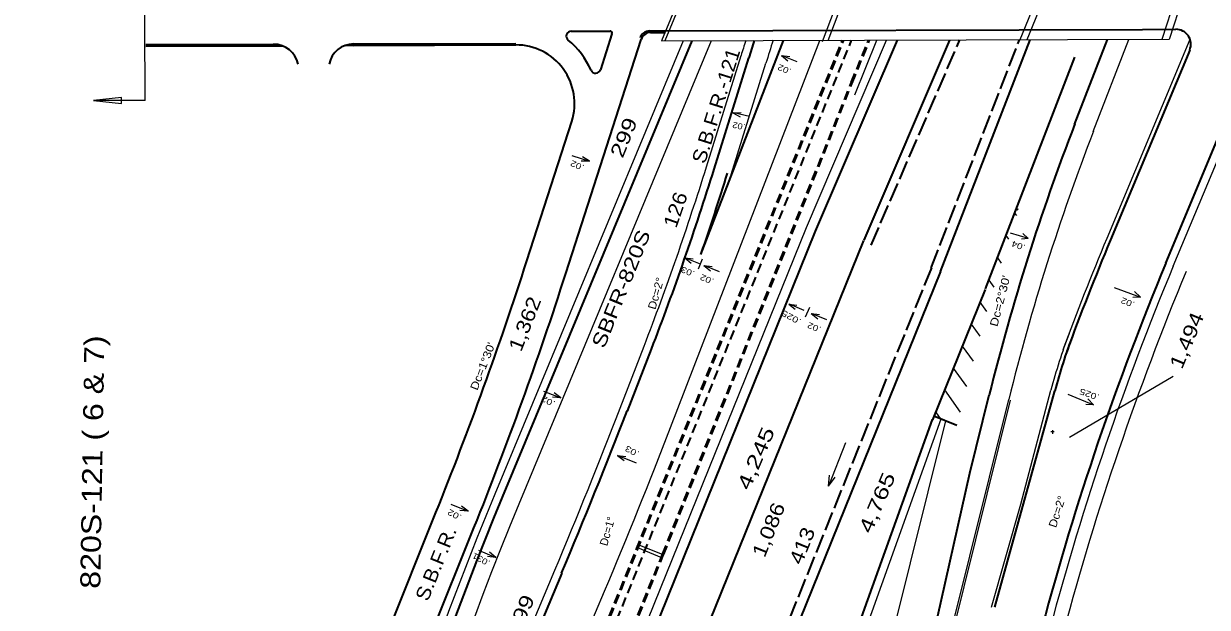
# Model space of a CAD drawing. Extents: x 2354993 to 2372084, y 6966390 to 6990057.
# Drawn here: x 2364091 to 2365274, y 6979897 to 6980481 of the extents above; entities that cross this region are included whole.
import ezdxf

# ---------------------------------------------------------------- set-up
doc = ezdxf.new("R2010")
doc.units = 0
doc.header["$LTSCALE"] = 3.2
doc.linetypes.add('LONG_DASHED', pattern=[7.5, 6, -1.5])
doc.linetypes.add('MEDIUM_DASHED', pattern=[4.5, 3, -1.5])
for name, color, linetype, lineweight in [('1', 7, 'Continuous', 13), ('12', 7, 'Continuous', 13), ('13', 7, 'Continuous', 13), ('14', 7, 'Continuous', 13), ('15', 7, 'Continuous', 13), ('17', 7, 'Continuous', 13), ('19', 7, 'Continuous', 13), ('2', 7, 'Continuous', 35), ('23', 7, 'Continuous', 13), ('4', 7, 'Continuous', 13), ('5', 7, 'Continuous', 35), ('63', 7, 'Continuous', 35), ('7', 7, 'Continuous', 13), ('9', 7, 'Continuous', 13)]:
    doc.layers.add(name, color=color, linetype=linetype, lineweight=lineweight)

msp = doc.modelspace()

# ---------------------------------------------------------------- linework, layer by layer
at = {"layer": '1', "lineweight": 35}
for p, q in [((2365083.088, 6980295.695), (2365084.953, 6980294.974)), ((2365051.927, 6980215.049), (2364999.207, 6980084.818))]:
    msp.add_line(p, q, dxfattribs=at)
at = {"layer": '1'}
for p, q in [((2365121.023, 6980072.57), (2365117.523, 6980072.57)), ((2365119.273, 6980074.32), (2365119.273, 6980070.82))]:
    msp.add_line(p, q, dxfattribs=at)
at = {"layer": '12'}
for p, q in [((2364889.34, 6980463.063), (2364934.323, 6980581.712)), ((2364895.069, 6980464.071), (2364938.998, 6980579.939)), ((2365133.691, 6980580.838), (2365086.673, 6980464.691)), ((2365140.767, 6980580.861), (2365093.748, 6980464.714)), ((2365273.39, 6980581.292), (2365235.902, 6980464.902)), ((2365263.831, 6980574.448), (2365228.608, 6980465.09)), ((2364704.438, 6979956.949), (2364728.538, 6979947.192))]:
    msp.add_line(p, q, dxfattribs=at)
at = {"layer": '13', "lineweight": 35}
for p, q in [((2365036.612, 6980031.444), (2365056.061, 6980109.786)), ((2364922.585, 6979522.917), (2365036.612, 6980031.444))]:
    msp.add_line(p, q, dxfattribs=at)
at = {"layer": '14'}
msp.add_line((2364895.323, 6980018.418), (2364901.939, 6980027.303), dxfattribs=at)
msp.add_lwpolyline([(2364912.252, 6980061.865), (2364895.323, 6980018.418), (2364896.266, 6980029.456)], dxfattribs=at)
at = {"layer": '15'}
msp.add_line((2364212.059, 6980404.032), (2364160.649, 6980403.865), dxfattribs=at)
msp.add_lwpolyline([(2364212.059, 6980404.032), (2364211.303, 6980637.104), (2364159.893, 6980636.937), (2364187.903, 6980634.029), (2364187.883, 6980640.028), (2364159.893, 6980636.937)], dxfattribs=at)
msp.add_lwpolyline([(2364160.649, 6980403.865), (2364188.659, 6980400.956), (2364188.639, 6980406.955)], close=True, dxfattribs=at)
at = {"layer": '17'}
for p, q in [((2365095.189, 6980265.952), (2365077.196, 6980271.228)), ((2365095.104, 6980266.029), (2365089.771, 6980271.008)), ((2365094.987, 6980266.028), (2365088.195, 6980265.248))]:
    msp.add_line(p, q, dxfattribs=at)
at = {"layer": '19'}
for p, q in [((2364848.319, 6980448.928), (2364854.815, 6980443.747)), ((2364848.319, 6980448.928), (2364856.571, 6980447.946)), ((2364863.906, 6980442.526), (2364849.11, 6980448.709)), ((2364799.753, 6980391.639), (2364808.048, 6980392.134)), ((2364799.753, 6980391.639), (2364807.064, 6980387.691)), ((2364816.228, 6980388.1), (2364800.57, 6980391.564)), ((2364638.595, 6980348.957), (2364656.429, 6980343.169)), ((2364656.429, 6980343.169), (2364648.126, 6980343.473)), ((2364656.429, 6980343.169), (2364649.532, 6980347.801)), ((2364751.674, 6980246.584), (2364758.17, 6980241.403)), ((2364751.674, 6980246.584), (2364759.926, 6980245.602)), ((2364767.261, 6980240.182), (2364752.465, 6980246.365)), ((2364769.185, 6980245.227), (2364764.875, 6980235.276)), ((2364770.828, 6980238.995), (2364777.324, 6980233.814)), ((2364770.828, 6980238.995), (2364779.08, 6980238.013)), ((2364786.415, 6980232.593), (2364771.619, 6980238.776)), ((2364855.541, 6980200.419), (2364862.037, 6980195.238)), ((2364855.541, 6980200.419), (2364863.793, 6980199.437)), ((2364871.128, 6980194.017), (2364856.332, 6980200.2)), ((2364876.405, 6980197.169), (2364872.095, 6980187.218)), ((2365207.175, 6980207.287), (2365199.555, 6980207.167)), ((2364878.048, 6980190.937), (2364884.544, 6980185.756)), ((2364878.048, 6980190.937), (2364886.3, 6980189.955)), ((2364893.635, 6980184.535), (2364878.839, 6980190.718)), ((2364610.341, 6980113.456), (2364627.785, 6980106.582)), ((2364627.785, 6980106.582), (2364619.516, 6980107.397)), ((2364627.785, 6980106.582), (2364621.186, 6980111.63)), ((2365160.351, 6980099.839), (2365152.732, 6980099.987)), ((2364684.446, 6980049.11), (2364692.709, 6980048.216)), ((2364517.739, 6980000.366), (2364535.115, 6979993.323)), ((2364535.115, 6979993.323), (2364528.565, 6979998.435)), ((2364535.115, 6979993.323), (2364526.855, 6979994.218)), ((2364545.495, 6979954.387), (2364562.777, 6979947.116)), ((2364562.777, 6979947.116), (2364556.295, 6979952.313)), ((2364562.777, 6979947.116), (2364554.529, 6979948.119))]:
    msp.add_line(p, q, dxfattribs=at)
for points in [[(2365181.045, 6980216.968), (2365207.175, 6980207.287), (2365201.372, 6980212.914)], [(2365134.575, 6980110.427), (2365160.351, 6980099.839), (2365154.747, 6980105.667)], [(2364703.322, 6980041.457), (2364684.446, 6980049.11), (2364690.995, 6980044)]]:
    msp.add_lwpolyline(points, dxfattribs=at)
at = {"layer": '2'}
for p, q in [((2364638.192, 6980473.229), (2364676.956, 6980473.353)), ((2364678.866, 6980470.741), (2364667.27, 6980434.672)), ((2364716.429, 6980473.483), (2365209.079, 6980475.077)), ((2364717.51, 6980471.986), (2364731.864, 6980472.033)), ((2364758.63, 6980463.629), (2364569.087, 6980007.233)), ((2364632.777, 6980231.022), (2364708.023, 6980465.047)), ((2364767.688, 6980249.927), (2364850.216, 6980463.926)), ((2364882.46, 6980273.331), (2364964.36, 6980464.295)), ((2364930.859, 6980264.426), (2365016.654, 6980464.464)), ((2365007.434, 6980233.06), (2365096.929, 6980464.724)), ((2364780.996, 6980335.421), (2364815.568, 6980446.589)), ((2365052.209, 6980215.763), (2365141.704, 6980447.427)), ((2364593.745, 6980243.573), (2364638.621, 6980383.141)), ((2364658.462, 6979719.253), (2364882.46, 6980273.331)), ((2364697.647, 6979688.336), (2364930.731, 6980264.109)), ((2365007.434, 6980233.06), (2364819.815, 6979769.595)), ((2364694.499, 6980093.497), (2364718.352, 6980155.347)), ((2364345.135, 6979599.119), (2364502.883, 6979991.918)), ((2364459.929, 6979774.94), (2364540.926, 6979976.626)), ((2364518.842, 6979669.717), (2364629.05, 6979931.257))]:
    msp.add_line(p, q, dxfattribs=at)
at = {"layer": '2', "linetype": 'LONG_DASHED'}
for p, q in [((2364937.909, 6980259.273), (2365026.649, 6980464.497)), ((2364998.106, 6980236.664), (2365086.195, 6980464.689)), ((2364998.165, 6980236.812), (2364810.546, 6979773.347))]:
    msp.add_line(p, q, dxfattribs=at)
at = {"layer": '2', "lineweight": 13}
msp.add_line((2365256.568, 6980465.111), (2365173.563, 6980266.128), dxfattribs=at)
at = {"layer": '2'}
for centre, radius, start, end in [((2364638.208, 6980468.229), 5, 90.18352, 230.55088), ((2364676.962, 6980471.353), 2, 342.17766, 90.18286), ((2364716.461, 6980463.483), 10, 90.18543, 162.29546), ((2364717.543, 6980461.986), 10, 90.18655, 162.17584), ((2364582.929, 6980401.048), 58.5, 342.17569, 90.18757), ((2364582.928, 6980401.048), 82, 23.83292, 50.55088), ((2370300.051, 6978740.971), 5743.578, 162.54462, 162.72484), ((2364662.51, 6980436.202), 5, 203.83292, 342.17739), ((2362045.437, 6981186.146), 2864.789, 338.91107, 342.72496), ((2362045.437, 6981186.146), 2878.788, 341.04639, 342.72496), ((2360994.978, 6981400.695), 3780.219, 338.11957, 342.17569), ((2360994.975, 6981400.684), 3821.219, 338.11954, 342.17584), ((2359382.264, 6982142.156), 5693.004, 337.15034, 338.91091), ((2367605.673, 6978746.13), 3288.045, 157.44674, 182.51497)]:
    msp.add_arc(centre, radius, start, end, dxfattribs=at)
at = {"layer": '2', "lineweight": 13}
for centre, radius, start, end in [((2367865.717, 6979143.099), 2917, 157.35659, 159.70903), ((2365704.789, 6979956.656), 608, 159.3693, 164.95986)]:
    msp.add_arc(centre, radius, start, end, dxfattribs=at)
at = {"layer": '23'}
msp.add_arc((2367865.518, 6979143.17), 2830.789, 157.35649, 165.06774, dxfattribs=at)
at = {"layer": '4'}
for p, q in [((2364749.956, 6980463.601), (2364561.699, 6980010.301)), ((2364778.146, 6980463.692), (2364585.71, 6980000.329)), ((2364737.418, 6980076.945), (2364886.702, 6980464.044)), ((2364773.357, 6980337.797), (2364807.929, 6980448.965)), ((2364798.185, 6980330.076), (2364832.756, 6980441.239)), ((2364687.035, 6980096.375), (2364710.887, 6980158.227)), ((2364511.47, 6979672.823), (2364621.678, 6979934.363)), ((2364586.141, 6979710.964), (2364671.441, 6979913.394))]:
    msp.add_line(p, q, dxfattribs=at)
for centre, radius, start, end in [((2370300.051, 6978740.971), 5751.578, 162.56997, 162.72484), ((2370300.048, 6978740.957), 5725.578, 162.48367, 162.72475), ((2362045.437, 6981186.146), 2856.789, 338.91107, 342.72496), ((2359382.264, 6982142.156), 5685.578, 337.15034, 338.91091), ((2359382.265, 6982142.155), 5739.578, 337.15034, 338.91091), ((2367605.673, 6978746.13), 3296.044, 157.44674, 174.9586), ((2367605.673, 6978746.13), 3270.045, 157.44674, 184.53246)]:
    msp.add_arc(centre, radius, start, end, dxfattribs=at)
at = {"layer": '5', "lineweight": 13}
for p, q in [((2364776.569, 6980579.679), (2364728.333, 6980463.531)), ((2364779.822, 6980579.689), (2364731.586, 6980463.541)), ((2364728.333, 6980463.531), (2365235.989, 6980465.174)), ((2364873.225, 6980277.168), (2364953.464, 6980464.26)), ((2364921.552, 6980409.674), (2364943.79, 6980464.228)), ((2365160.069, 6980372.867), (2365195.679, 6980465.044)), ((2365240.01, 6980238.403), (2365312.776, 6980412.838)), ((2365081.383, 6980291.281), (2365083.112, 6980288.869)), ((2364638.255, 6979695.95), (2364873.225, 6980277.167)), ((2365072.766, 6980268.977), (2365075.393, 6980265.315)), ((2365064.15, 6980246.673), (2365067.869, 6980241.487)), ((2365055.534, 6980224.369), (2365060.547, 6980217.379)), ((2365046.76, 6980202.285), (2365053.43, 6980192.984)), ((2365037.88, 6980180.349), (2365046.525, 6980168.294)), ((2365029, 6980158.413), (2365039.837, 6980143.302)), ((2365020.12, 6980136.477), (2365033.372, 6980117.998)), ((2365239.993, 6980127.96), (2365136.183, 6980067.213)), ((2365011.24, 6980114.541), (2365027.042, 6980092.506)), ((2365087.473, 6980000.245), (2365117.617, 6980114.429)), ((2364760.631, 6978828.473), (2365077.413, 6980104.485)), ((2364952, 6979607.617), (2365075.472, 6980104.967)), ((2365002.36, 6980092.605), (2365007.081, 6980086.022)), ((2364704.339, 6978842.448), (2365012.522, 6980083.82)), ((2364905.475, 6979799.995), (2365008.116, 6980085.603)), ((2365058.33, 6979897.253), (2365087.473, 6980000.245)), ((2364705.563, 6979959.728), (2364729.664, 6979949.972))]:
    msp.add_line(p, q, dxfattribs=at)
at = {"layer": '5'}
for p, q in [((2365209.08, 6980475.089), (2365242.552, 6980475.198)), ((2364212.913, 6980459.849), (2364275.143, 6980460.051)), ((2364212.918, 6980458.349), (2364275.148, 6980458.551)), ((2364275.143, 6980460.041), (2364340.584, 6980460.255)), ((2364275.148, 6980458.541), (2364349.118, 6980458.783)), ((2364412.06, 6980458.989), (2364561.033, 6980459.477)), ((2364420.584, 6980460.517), (2364582.732, 6980461.048)), ((2364420.589, 6980459.017), (2364582.737, 6980459.548)), ((2365141.413, 6980380.074), (2365174.211, 6980464.974)), ((2365256.444, 6980454.423), (2365177.254, 6980264.588)), ((2365232.627, 6980241.483), (2365286.877, 6980371.531)), ((2365061.659, 6979897.318), (2365121.53, 6980113.58)), ((2364897.947, 6979802.7), (2364999.406, 6980085.023)), ((2365000.735, 6980088.591), (2365023.757, 6980079.271))]:
    msp.add_line(p, q, dxfattribs=at)
at = {"layer": '5', "linetype": 'MEDIUM_DASHED', "lineweight": 53}
for p, q in [((2364568.363, 6979620.801), (2364909.746, 6980464.118)), ((2364918.426, 6980421.599), (2364935.672, 6980464.202)), ((2364729.664, 6979949.972), (2364918.426, 6980421.599)), ((2364705.011, 6979889.07), (2364729.664, 6979949.972))]:
    msp.add_line(p, q, dxfattribs=at)
at = {"layer": '5', "linetype": 'MEDIUM_DASHED'}
msp.add_line((2364575.778, 6979617.799), (2364918.388, 6980464.146), dxfattribs=at)
at = {"layer": '5'}
for centre, radius, start, end in [((2365242.6, 6980460.198), 15, 337.35659, 90.1868), ((2364340.666, 6980435.255), 25, 11.74837, 90.18759), ((2364420.666, 6980435.517), 25, 90.18759, 168.62957), ((2367257.079, 6979563.363), 2267.831, 158.87757, 166.05765), ((2367865.717, 6979143.099), 2913, 157.35659, 159.70501), ((2367865.518, 6979143.17), 2852.789, 157.35649, 165.06774), ((2365700.977, 6979957.883), 600, 159.37414, 164.95986)]:
    msp.add_arc(centre, radius, start, end, dxfattribs=at)
at = {"layer": '5', "lineweight": 13}
for centre, radius, start, end in [((2367257.079, 6979563.363), 2247.831, 158.87757, 166.05765), ((2367865.518, 6979143.17), 2844.789, 157.35649, 165.06774)]:
    msp.add_arc(centre, radius, start, end, dxfattribs=at)
at = {"layer": '9'}
msp.add_arc((2360722.521, 6984327.136), 5729.573, 359.50797, 359.50797, dxfattribs=at)

# ---------------------------------------------------------------- texts
at = {"layer": '13'}
for s, rotation, width, p in [('S.B.F.R.-121', 72.597, 1.1, (2364771.772, 6980339.891)), ('299', 68.045, 1.3, (2364689.513, 6980345.521)), ('126', 70.784, 1.15, (2364743.036, 6980275.514)), ('SBFR-820S', 68.045, 1.25, (2364671.074, 6980155.164)), ('1,362', 68.675, 1.2, (2364588.006, 6980151.93)), ('1,494', 67.399, 1.25, (2365248.635, 6980134.416)), ('4,245', 66.79, 1.4, (2364816.252, 6980013.358)), ('4,765', 66.79, 1.35, (2364937.849, 6979970.148)), ('1,086', 68.045, 1.2, (2364831.45, 6979946.104)), ('S.B.F.R.', 67.932, 1.1, (2364494.763, 6979902.309)), ('413', 68.045, 1.2, (2364868.422, 6979938.929)), ('2,699', 66.79, 1.3, (2364578.039, 6979849.891))]:
    msp.add_text(s, height=14, rotation=rotation, dxfattribs=dict(at, width=width)).set_placement(p)
at = {"layer": '17'}
for s, height, rotation, width, p in [('.04', 6, 159.81, 1.25, (2365092.825, 6980259.286)), ('Dc=2°', 8, 74.075, 1.1, (2364722.249, 6980194.391)), ("Dc=2°30'", 8, 75.548, 1.2, (2365064.143, 6980177.299)), ("Dc=1°30'", 8, 68.676, 1.15, (2364544.242, 6980113.558))]:
    msp.add_text(s, height=height, rotation=rotation, dxfattribs=dict(at, width=width)).set_placement(p)
msp.add_text('Dc=1°', height=8, rotation=74.075, dxfattribs=at).set_placement((2364674.079, 6979958.021))
at = {"layer": '19'}
for s, height, rotation, width, p in [('.02', 6, 157.459, 1.25, (2364858.898, 6980435.228)), ('.02', 6, 167.664, 1.15, (2364812.592, 6980380.03)), ('.02', 5.999, 156.625, 1.25, (2364651.739, 6980338.969)), ('.03', 6, 157.459, 1.25, (2364762.253, 6980232.884)), ('.02', 6, 157.459, 1.25, (2364781.407, 6980225.295)), ('.02', 6, 158.402, 1.25, (2365202.083, 6980202.224)), ('.025', 6, 151.78, 1.35, (2364868.851, 6980184.837)), ('.02', 6, 157.459, 1.25, (2364888.627, 6980177.237)), ('.025', 6, 160.402, 1.3, (2365166.754, 6980109.548)), ('.02', 5.999, 153.098, 1.3, (2364622.846, 6980102.679)), ('.03', 6, 152.03, 1.3, (2364706.812, 6980052.483)), ('.02', 5.999, 152.545, 1.3, (2364529.292, 6979989.097)), ('.031', 5.999, 151.789, 1.2, (2364557.75, 6979943.327))]:
    msp.add_text(s, height=height, rotation=rotation, dxfattribs=dict(at, width=width)).set_placement(p)
at = {"layer": '63', "width": 1.2}
msp.add_text('820S-121 ( 6 & 7)', height=20, rotation=89.044, dxfattribs=at).set_placement((2364167.268, 6979915.681))
at = {"layer": '7', "width": 1.1}
msp.add_text('Dc=2°', height=7.999, rotation=72.088, dxfattribs=at).set_placement((2365122.773, 6979976.265))

doc.saveas('drawing.dxf')
